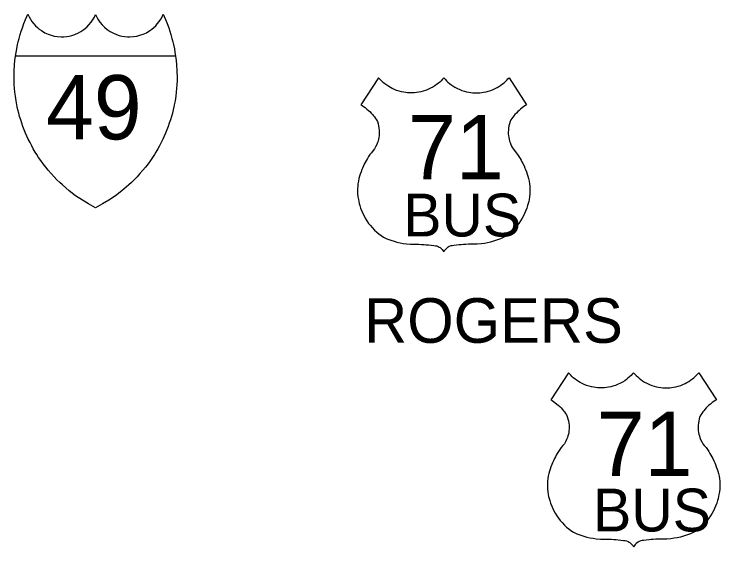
# Model space of a CAD drawing. Extents: x 6028647 to 6035072, y 5366486 to 5368495.
# Drawn here: x 6029149.6 to 6029253.9, y 5368034.5 to 5368113.3 of the extents above; entities that cross this region are included whole.
import ezdxf

# ---------------------------------------------------------------- set-up
doc = ezdxf.new("R2010")
doc.units = 0
for name, color, linetype in [('22', 7, 'Continuous'), ('23', 7, 'Continuous'), ('25', 7, 'Continuous')]:
    doc.layers.add(name, color=color, linetype=linetype)

msp = doc.modelspace()

# ---------------------------------------------------------------- linework, layer by layer
at = {"layer": '22'}
for points in [[(6029213.12, 5368103.89), (6029212.93, 5368103.67), (6029212.74, 5368103.47), (6029212.52, 5368103.27), (6029212.29, 5368103.07), (6029212.07, 5368102.9), (6029211.8, 5368102.71), (6029211.51, 5368102.53), (6029211.17, 5368102.35), (6029210.75, 5368102.15), (6029210.43, 5368102.03), (6029210.07, 5368101.91), (6029209.73, 5368101.82), (6029209.43, 5368101.76), (6029209.1, 5368101.71), (6029208.81, 5368101.68), (6029208.4, 5368101.66), (6029208.07, 5368101.66), (6029207.78, 5368101.68), (6029207.5, 5368101.71), (6029207.22, 5368101.75), (6029206.87, 5368101.82), (6029206.55, 5368101.91), (6029206.15, 5368102.04), (6029205.82, 5368102.17), (6029205.52, 5368102.31), (6029205.24, 5368102.45), (6029204.98, 5368102.6), (6029204.69, 5368102.79), (6029204.43, 5368102.99), (6029204.2, 5368103.17), (6029204.01, 5368103.34), (6029203.82, 5368103.53), (6029203.63, 5368103.73), (6029203.47, 5368103.91), (6029200.87, 5368099.89), (6029201.06, 5368099.78), (6029201.28, 5368099.64), (6029201.49, 5368099.49), (6029201.77, 5368099.27), (6029201.99, 5368099.08), (6029202.19, 5368098.9), (6029202.39, 5368098.69), (6029202.6, 5368098.46), (6029202.74, 5368098.29), (6029202.89, 5368098.1), (6029203.04, 5368097.89), (6029203.18, 5368097.67), (6029203.31, 5368097.42), (6029203.41, 5368097.11), (6029203.49, 5368096.8), (6029203.55, 5368096.46), (6029203.58, 5368096.16), (6029203.59, 5368095.86), (6029203.58, 5368095.58), (6029203.56, 5368095.36), (6029203.53, 5368095.08), (6029203.48, 5368094.83), (6029203.41, 5368094.55), (6029203.33, 5368094.31), (6029203.22, 5368094.03), (6029203.05, 5368093.68), (6029202.88, 5368093.4), (6029202.67, 5368093.15), (6029202.42, 5368092.82), (6029202.21, 5368092.54), (6029202.02, 5368092.25), (6029201.84, 5368091.97), (6029201.69, 5368091.72), (6029201.56, 5368091.48), (6029201.41, 5368091.2), (6029201.26, 5368090.87), (6029201.12, 5368090.55), (6029201.02, 5368090.32), (6029200.9, 5368090.01), (6029200.78, 5368089.64), (6029200.68, 5368089.33), (6029200.58, 5368088.99), (6029200.5, 5368088.59), (6029200.44, 5368088.24), (6029200.4, 5368087.87), (6029200.37, 5368087.48), (6029200.37, 5368087.1), (6029200.39, 5368086.73), (6029200.43, 5368086.3), (6029200.5, 5368085.89), (6029200.57, 5368085.59), (6029200.64, 5368085.31), (6029200.73, 5368085.01), (6029200.84, 5368084.63), (6029201.02, 5368084.16), (6029201.16, 5368083.82), (6029201.34, 5368083.47), (6029201.52, 5368083.13), (6029201.77, 5368082.74), (6029202.02, 5368082.37), (6029202.27, 5368082.06), (6029202.54, 5368081.74), (6029202.9, 5368081.36), (6029203.21, 5368081.08), (6029203.52, 5368080.82)], [(6029213.12, 5368103.89), (6029213.32, 5368103.67), (6029213.51, 5368103.47), (6029213.72, 5368103.27), (6029213.95, 5368103.07), (6029214.18, 5368102.9), (6029214.45, 5368102.71), (6029214.74, 5368102.53), (6029215.07, 5368102.35), (6029215.49, 5368102.15), (6029215.81, 5368102.03), (6029216.18, 5368101.91), (6029216.51, 5368101.82), (6029216.82, 5368101.76), (6029217.14, 5368101.71), (6029217.44, 5368101.68), (6029217.85, 5368101.66), (6029218.18, 5368101.66), (6029218.47, 5368101.68), (6029218.74, 5368101.71), (6029219.02, 5368101.75), (6029219.37, 5368101.82), (6029219.7, 5368101.91), (6029220.09, 5368102.04), (6029220.43, 5368102.17), (6029220.73, 5368102.31), (6029221.01, 5368102.45), (6029221.26, 5368102.6), (6029221.55, 5368102.79), (6029221.81, 5368102.99), (6029222.04, 5368103.17), (6029222.23, 5368103.34), (6029222.43, 5368103.53), (6029222.62, 5368103.73), (6029222.77, 5368103.91), (6029225.37, 5368099.89), (6029225.19, 5368099.78), (6029224.96, 5368099.64), (6029224.76, 5368099.49), (6029224.48, 5368099.27), (6029224.25, 5368099.08), (6029224.06, 5368098.9), (6029223.86, 5368098.69), (6029223.65, 5368098.46), (6029223.5, 5368098.29), (6029223.36, 5368098.1), (6029223.21, 5368097.89), (6029223.06, 5368097.67), (6029222.93, 5368097.42), (6029222.83, 5368097.11), (6029222.75, 5368096.8), (6029222.7, 5368096.46), (6029222.67, 5368096.16), (6029222.65, 5368095.86), (6029222.66, 5368095.58), (6029222.68, 5368095.36), (6029222.72, 5368095.08), (6029222.77, 5368094.83), (6029222.84, 5368094.55), (6029222.92, 5368094.31), (6029223.03, 5368094.03), (6029223.19, 5368093.68), (6029223.37, 5368093.4), (6029223.58, 5368093.15), (6029223.83, 5368092.82), (6029224.04, 5368092.54), (6029224.23, 5368092.25), (6029224.41, 5368091.97), (6029224.55, 5368091.72), (6029224.68, 5368091.48), (6029224.83, 5368091.2), (6029224.99, 5368090.87), (6029225.13, 5368090.55), (6029225.23, 5368090.32), (6029225.34, 5368090.01), (6029225.47, 5368089.64), (6029225.57, 5368089.33), (6029225.66, 5368088.99), (6029225.75, 5368088.59), (6029225.81, 5368088.24), (6029225.85, 5368087.87), (6029225.87, 5368087.48), (6029225.87, 5368087.1), (6029225.86, 5368086.73), (6029225.81, 5368086.3), (6029225.75, 5368085.89), (6029225.68, 5368085.59), (6029225.61, 5368085.31), (6029225.52, 5368085.01), (6029225.4, 5368084.63), (6029225.23, 5368084.16), (6029225.08, 5368083.82), (6029224.91, 5368083.47), (6029224.72, 5368083.13), (6029224.48, 5368082.74), (6029224.22, 5368082.37), (6029223.98, 5368082.06), (6029223.7, 5368081.74), (6029223.34, 5368081.36), (6029223.04, 5368081.08), (6029222.72, 5368080.82)], [(6029203.52, 5368080.82), (6029203.85, 5368080.57), (6029204.24, 5368080.32), (6029204.73, 5368080.1), (6029205.3, 5368079.88), (6029205.77, 5368079.72), (6029206.19, 5368079.61), (6029206.67, 5368079.5), (6029207.12, 5368079.41), (6029207.6, 5368079.35), (6029208.21, 5368079.3), (6029208.67, 5368079.28), (6029209.07, 5368079.28), (6029209.46, 5368079.28), (6029209.84, 5368079.26), (6029210.21, 5368079.25), (6029210.53, 5368079.22), (6029210.85, 5368079.2), (6029211.25, 5368079.16), (6029211.64, 5368079.11), (6029211.88, 5368079.07), (6029212.08, 5368079.04), (6029212.31, 5368078.94), (6029212.45, 5368078.86), (6029212.57, 5368078.79), (6029212.73, 5368078.65), (6029212.88, 5368078.5), (6029213.01, 5368078.34), (6029213.12, 5368078.15)], [(6029222.72, 5368080.82), (6029222.4, 5368080.57), (6029222.01, 5368080.32), (6029221.52, 5368080.1), (6029220.94, 5368079.88), (6029220.47, 5368079.72), (6029220.05, 5368079.61), (6029219.57, 5368079.5), (6029219.13, 5368079.41), (6029218.64, 5368079.35), (6029218.04, 5368079.3), (6029217.57, 5368079.28), (6029217.17, 5368079.28), (6029216.79, 5368079.28), (6029216.4, 5368079.26), (6029216.03, 5368079.25), (6029215.71, 5368079.22), (6029215.4, 5368079.2), (6029215, 5368079.16), (6029214.6, 5368079.11), (6029214.37, 5368079.07), (6029214.17, 5368079.04), (6029213.93, 5368078.94), (6029213.8, 5368078.86), (6029213.68, 5368078.79), (6029213.52, 5368078.65), (6029213.36, 5368078.5), (6029213.24, 5368078.34), (6029213.12, 5368078.15)], [(6029241.19, 5368060.27), (6029240.99, 5368060.05), (6029240.81, 5368059.86), (6029240.59, 5368059.66), (6029240.36, 5368059.46), (6029240.14, 5368059.28), (6029239.87, 5368059.09), (6029239.57, 5368058.91), (6029239.24, 5368058.73), (6029238.82, 5368058.54), (6029238.5, 5368058.41), (6029238.14, 5368058.29), (6029237.8, 5368058.21), (6029237.5, 5368058.14), (6029237.17, 5368058.09), (6029236.87, 5368058.06), (6029236.47, 5368058.04), (6029236.13, 5368058.05), (6029235.84, 5368058.06), (6029235.57, 5368058.09), (6029235.29, 5368058.14), (6029234.94, 5368058.21), (6029234.62, 5368058.29), (6029234.22, 5368058.42), (6029233.89, 5368058.55), (6029233.59, 5368058.69), (6029233.31, 5368058.84), (6029233.05, 5368058.99), (6029232.76, 5368059.18), (6029232.5, 5368059.37), (6029232.27, 5368059.55), (6029232.08, 5368059.72), (6029231.89, 5368059.91), (6029231.69, 5368060.12), (6029231.54, 5368060.29), (6029228.94, 5368056.28), (6029229.13, 5368056.17), (6029229.35, 5368056.02), (6029229.56, 5368055.87), (6029229.84, 5368055.66), (6029230.06, 5368055.47), (6029230.26, 5368055.28), (6029230.46, 5368055.08), (6029230.66, 5368054.85), (6029230.81, 5368054.67), (6029230.96, 5368054.48), (6029231.11, 5368054.27), (6029231.25, 5368054.06), (6029231.38, 5368053.8), (6029231.48, 5368053.49), (6029231.56, 5368053.18), (6029231.62, 5368052.85), (6029231.65, 5368052.54), (6029231.66, 5368052.24), (6029231.65, 5368051.96), (6029231.63, 5368051.74), (6029231.6, 5368051.47), (6029231.55, 5368051.21), (6029231.47, 5368050.93), (6029231.4, 5368050.69), (6029231.29, 5368050.41), (6029231.12, 5368050.06), (6029230.95, 5368049.78), (6029230.74, 5368049.53), (6029230.48, 5368049.21), (6029230.28, 5368048.92), (6029230.08, 5368048.63), (6029229.91, 5368048.35), (6029229.76, 5368048.1), (6029229.63, 5368047.87), (6029229.48, 5368047.58), (6029229.33, 5368047.26), (6029229.18, 5368046.94), (6029229.09, 5368046.7), (6029228.97, 5368046.39), (6029228.85, 5368046.02), (6029228.75, 5368045.71), (6029228.65, 5368045.37), (6029228.56, 5368044.97), (6029228.51, 5368044.62), (6029228.46, 5368044.26), (6029228.44, 5368043.86), (6029228.44, 5368043.48), (6029228.46, 5368043.12), (6029228.5, 5368042.69), (6029228.57, 5368042.28), (6029228.63, 5368041.97), (6029228.71, 5368041.7), (6029228.79, 5368041.39), (6029228.91, 5368041.01), (6029229.09, 5368040.55), (6029229.23, 5368040.21), (6029229.4, 5368039.86), (6029229.59, 5368039.51), (6029229.84, 5368039.12), (6029230.09, 5368038.76), (6029230.33, 5368038.44), (6029230.61, 5368038.12), (6029230.97, 5368037.75), (6029231.28, 5368037.46), (6029231.59, 5368037.2)], [(6029241.19, 5368060.27), (6029241.39, 5368060.05), (6029241.58, 5368059.86), (6029241.79, 5368059.66), (6029242.02, 5368059.46), (6029242.25, 5368059.28), (6029242.52, 5368059.09), (6029242.81, 5368058.91), (6029243.14, 5368058.73), (6029243.56, 5368058.54), (6029243.88, 5368058.41), (6029244.25, 5368058.29), (6029244.58, 5368058.21), (6029244.89, 5368058.14), (6029245.21, 5368058.09), (6029245.51, 5368058.06), (6029245.92, 5368058.04), (6029246.25, 5368058.05), (6029246.54, 5368058.06), (6029246.81, 5368058.09), (6029247.09, 5368058.14), (6029247.44, 5368058.21), (6029247.76, 5368058.29), (6029248.16, 5368058.42), (6029248.49, 5368058.55), (6029248.8, 5368058.69), (6029249.08, 5368058.84), (6029249.33, 5368058.99), (6029249.62, 5368059.18), (6029249.88, 5368059.37), (6029250.11, 5368059.55), (6029250.3, 5368059.72), (6029250.5, 5368059.91), (6029250.69, 5368060.12), (6029250.84, 5368060.29), (6029253.44, 5368056.28), (6029253.25, 5368056.17), (6029253.03, 5368056.02), (6029252.82, 5368055.87), (6029252.54, 5368055.66), (6029252.32, 5368055.47), (6029252.12, 5368055.28), (6029251.92, 5368055.08), (6029251.72, 5368054.85), (6029251.57, 5368054.67), (6029251.42, 5368054.48), (6029251.28, 5368054.27), (6029251.13, 5368054.06), (6029251, 5368053.8), (6029250.9, 5368053.49), (6029250.82, 5368053.18), (6029250.77, 5368052.85), (6029250.73, 5368052.54), (6029250.72, 5368052.24), (6029250.73, 5368051.96), (6029250.75, 5368051.74), (6029250.79, 5368051.47), (6029250.84, 5368051.21), (6029250.91, 5368050.93), (6029250.99, 5368050.69), (6029251.09, 5368050.41), (6029251.26, 5368050.06), (6029251.44, 5368049.78), (6029251.64, 5368049.53), (6029251.9, 5368049.21), (6029252.11, 5368048.92), (6029252.3, 5368048.63), (6029252.47, 5368048.35), (6029252.62, 5368048.1), (6029252.75, 5368047.87), (6029252.9, 5368047.58), (6029253.06, 5368047.26), (6029253.2, 5368046.94), (6029253.29, 5368046.7), (6029253.41, 5368046.39), (6029253.54, 5368046.02), (6029253.64, 5368045.71), (6029253.73, 5368045.37), (6029253.82, 5368044.97), (6029253.88, 5368044.62), (6029253.92, 5368044.26), (6029253.94, 5368043.86), (6029253.94, 5368043.48), (6029253.93, 5368043.12), (6029253.88, 5368042.69), (6029253.81, 5368042.28), (6029253.75, 5368041.97), (6029253.68, 5368041.7), (6029253.59, 5368041.39), (6029253.47, 5368041.01), (6029253.3, 5368040.55), (6029253.15, 5368040.21), (6029252.98, 5368039.86), (6029252.79, 5368039.51), (6029252.55, 5368039.12), (6029252.29, 5368038.76), (6029252.05, 5368038.44), (6029251.77, 5368038.12), (6029251.41, 5368037.75), (6029251.11, 5368037.46), (6029250.79, 5368037.2)], [(6029231.59, 5368037.2), (6029231.91, 5368036.96), (6029232.31, 5368036.7), (6029232.8, 5368036.48), (6029233.37, 5368036.26), (6029233.84, 5368036.11), (6029234.26, 5368035.99), (6029234.74, 5368035.88), (6029235.19, 5368035.8), (6029235.67, 5368035.73), (6029236.28, 5368035.68), (6029236.74, 5368035.66), (6029237.14, 5368035.66), (6029237.53, 5368035.66), (6029237.91, 5368035.65), (6029238.28, 5368035.63), (6029238.6, 5368035.61), (6029238.91, 5368035.58), (6029239.32, 5368035.54), (6029239.71, 5368035.49), (6029239.95, 5368035.46), (6029240.14, 5368035.42), (6029240.38, 5368035.32), (6029240.52, 5368035.25), (6029240.63, 5368035.17), (6029240.8, 5368035.04), (6029240.95, 5368034.88), (6029241.08, 5368034.72), (6029241.19, 5368034.53)], [(6029250.79, 5368037.2), (6029250.47, 5368036.96), (6029250.08, 5368036.7), (6029249.59, 5368036.48), (6029249.01, 5368036.26), (6029248.54, 5368036.11), (6029248.12, 5368035.99), (6029247.64, 5368035.88), (6029247.19, 5368035.8), (6029246.71, 5368035.73), (6029246.1, 5368035.68), (6029245.64, 5368035.66), (6029245.24, 5368035.66), (6029244.86, 5368035.66), (6029244.47, 5368035.65), (6029244.1, 5368035.63), (6029243.78, 5368035.61), (6029243.47, 5368035.58), (6029243.06, 5368035.54), (6029242.67, 5368035.49), (6029242.43, 5368035.46), (6029242.24, 5368035.42), (6029242, 5368035.32), (6029241.87, 5368035.25), (6029241.75, 5368035.17), (6029241.59, 5368035.04), (6029241.43, 5368034.88), (6029241.31, 5368034.72), (6029241.19, 5368034.53)]]:
    msp.add_lwpolyline(points, dxfattribs=at)
at = {"layer": '23'}
for points in [[(6029149.83, 5368107.09), (6029149.91, 5368107.66), (6029150, 5368108.16), (6029150.13, 5368108.8), (6029150.23, 5368109.22), (6029150.36, 5368109.72), (6029150.52, 5368110.31), (6029150.67, 5368110.8), (6029150.84, 5368111.3), (6029151.07, 5368111.92), (6029151.3, 5368112.51), (6029151.49, 5368112.96), (6029151.65, 5368113.31), (6029151.83, 5368112.93), (6029152.03, 5368112.56), (6029152.25, 5368112.23), (6029152.54, 5368111.86), (6029152.77, 5368111.6), (6029153.05, 5368111.33), (6029153.33, 5368111.09), (6029153.64, 5368110.87), (6029154.13, 5368110.57), (6029154.63, 5368110.34), (6029155.09, 5368110.18), (6029155.54, 5368110.06), (6029156.02, 5368109.98), (6029156.59, 5368109.95), (6029156.95, 5368109.95), (6029157.38, 5368109.99), (6029157.76, 5368110.06), (6029158.16, 5368110.16), (6029158.57, 5368110.29), (6029159.11, 5368110.53), (6029159.49, 5368110.74), (6029159.93, 5368111.04), (6029160.35, 5368111.4), (6029160.66, 5368111.71), (6029161.01, 5368112.13), (6029161.3, 5368112.57), (6029161.47, 5368112.87), (6029161.65, 5368113.27)], [(6029161.65, 5368113.27), (6029161.84, 5368112.87), (6029162.01, 5368112.57), (6029162.3, 5368112.13), (6029162.65, 5368111.71), (6029162.96, 5368111.4), (6029163.38, 5368111.04), (6029163.81, 5368110.74), (6029164.19, 5368110.53), (6029164.74, 5368110.29), (6029165.15, 5368110.16), (6029165.55, 5368110.06), (6029165.93, 5368109.99), (6029166.35, 5368109.95), (6029166.72, 5368109.95), (6029167.28, 5368109.98), (6029167.77, 5368110.06), (6029168.22, 5368110.18), (6029168.67, 5368110.34), (6029169.17, 5368110.57), (6029169.67, 5368110.87), (6029169.97, 5368111.09), (6029170.26, 5368111.33), (6029170.54, 5368111.6), (6029170.77, 5368111.86), (6029171.06, 5368112.23), (6029171.28, 5368112.56), (6029171.48, 5368112.93), (6029171.65, 5368113.31), (6029171.81, 5368112.96), (6029172.01, 5368112.51), (6029172.24, 5368111.92), (6029172.46, 5368111.3), (6029172.63, 5368110.8), (6029172.78, 5368110.31), (6029172.95, 5368109.72), (6029173.07, 5368109.22), (6029173.17, 5368108.8), (6029173.3, 5368108.16), (6029173.39, 5368107.66), (6029173.48, 5368107.09)], [(6029161.65, 5368084.69), (6029160.62, 5368085.24), (6029159.71, 5368085.79), (6029158.7, 5368086.46), (6029157.77, 5368087.17), (6029156.74, 5368088.05), (6029156.36, 5368088.4), (6029155.93, 5368088.83), (6029155.52, 5368089.24), (6029155.08, 5368089.73), (6029154.65, 5368090.23), (6029154.29, 5368090.67), (6029153.9, 5368091.18), (6029153.54, 5368091.68), (6029153.23, 5368092.13), (6029152.96, 5368092.55), (6029152.74, 5368092.91), (6029152.44, 5368093.41), (6029152.21, 5368093.83), (6029151.96, 5368094.31), (6029151.71, 5368094.81), (6029151.5, 5368095.27), (6029151.31, 5368095.72), (6029151.1, 5368096.22), (6029150.92, 5368096.68), (6029150.75, 5368097.17), (6029150.59, 5368097.67), (6029150.43, 5368098.19), (6029150.3, 5368098.69), (6029150.18, 5368099.16), (6029150.08, 5368099.58), (6029150.02, 5368099.89), (6029149.91, 5368100.49), (6029149.8, 5368101.18), (6029149.72, 5368101.76), (6029149.67, 5368102.37), (6029149.64, 5368102.87), (6029149.62, 5368103.5), (6029149.61, 5368104.08), (6029149.62, 5368104.73), (6029149.64, 5368105.16), (6029149.66, 5368105.55), (6029149.68, 5368105.8), (6029149.74, 5368106.44), (6029149.83, 5368107.09)], [(6029173.48, 5368107.09), (6029149.83, 5368107.09)], [(6029173.48, 5368107.09), (6029173.56, 5368106.44), (6029173.62, 5368105.8), (6029173.64, 5368105.55), (6029173.67, 5368105.16), (6029173.68, 5368104.73), (6029173.7, 5368104.08), (6029173.69, 5368103.5), (6029173.67, 5368102.87), (6029173.64, 5368102.37), (6029173.58, 5368101.76), (6029173.51, 5368101.18), (6029173.4, 5368100.49), (6029173.29, 5368099.89), (6029173.22, 5368099.58), (6029173.13, 5368099.16), (6029173.01, 5368098.69), (6029172.87, 5368098.19), (6029172.72, 5368097.67), (6029172.55, 5368097.17), (6029172.38, 5368096.68), (6029172.21, 5368096.22), (6029172, 5368095.72), (6029171.81, 5368095.27), (6029171.59, 5368094.81), (6029171.35, 5368094.31), (6029171.09, 5368093.83), (6029170.86, 5368093.41), (6029170.57, 5368092.91), (6029170.34, 5368092.55), (6029170.07, 5368092.13), (6029169.77, 5368091.68), (6029169.41, 5368091.18), (6029169.02, 5368090.67), (6029168.66, 5368090.23), (6029168.22, 5368089.73), (6029167.78, 5368089.24), (6029167.38, 5368088.83), (6029166.95, 5368088.4), (6029166.56, 5368088.05), (6029165.54, 5368087.17), (6029164.6, 5368086.46), (6029163.6, 5368085.79), (6029162.69, 5368085.24), (6029161.65, 5368084.69)]]:
    msp.add_lwpolyline(points, dxfattribs=at)

# ---------------------------------------------------------------- texts
at = {"layer": '22'}
for s, height, p in [('49', 9.504, (6029154.33, 5368094.79)), ('71', 9.504, (6029207.85, 5368088.89)), ('BUS', 6.336, (6029207.14, 5368080.43)), ('71', 9.504, (6029235.74, 5368045.01)), ('BUS', 6.336, (6029235.2, 5368036.81))]:
    msp.add_text(s, height=height, dxfattribs=at).set_placement(p)
at = {"layer": '25'}
msp.add_text('ROGERS', height=6.6, dxfattribs=at).set_placement((6029201.35, 5368064.71))

doc.saveas('drawing.dxf')
